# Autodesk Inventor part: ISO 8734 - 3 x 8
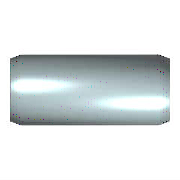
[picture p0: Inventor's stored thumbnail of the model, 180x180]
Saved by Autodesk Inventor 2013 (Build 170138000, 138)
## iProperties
Created: 2012-02
Part Number: ISO 8734 - 3 x 8
Material: Stahl
Description: Zylinderstifte aus gehärtetem Martensit-Edelstahl (Passstifte)
Document SubType Name: Modeling
Standard: ISO 8734
Designer: rYan
Standards Organization: BSI
Language: de-DE
Size Designation: 3 x 8
Categories: <MemberInstance><Categories><Category DisplayName="Verbindungselemente" InternalName="e4da775c-781d-43d5-af7c-5136215cf5a6" Mnemonic="FSTN"><Category DisplayNam
Density: 7.85 g/cm^3
IsCustomPart: 1
Author: rYan
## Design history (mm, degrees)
sketch "Skizze"
  geometry: C1 r 1.5 at (0, 0); 1 further point
  constraints: 1 centre point, 1 coincident
  dimensions: "d1" = 3 diameter of C1 (= NND)
extrude "Körper" new body sketch "Skizze" distance "d2" = 6; taper "d3" = 0 deg
chamfer "Skizze2" distance "d8" = 0.5 (= PHH); stored, may be unused: angle "d9" = 15 deg (= FAWI), second distance "d12" = 0.5 (= PHH)
body "Solid1"
chamfer "Fase1" distance "d4" = 0.5 (= PHH); stored, may be unused: angle "d5" = 15 deg (= FAWI), second distance "d11" = 0.5 (= PHH)
other parameters: "NND" = 3 [user parameter; used in 1 equation term], "NLG" = 8 [user parameter], "PHH" = 0.5 [user parameter; used in 5 equation terms], "FAWI" = 15 deg [user parameter; used in 2 equation terms], "d13" = 0, "d15" = 0, "d16" = 0, "PHH2" = 0.5 (= PHH) [user parameter], "FAWI2" = 15 deg [user parameter]
